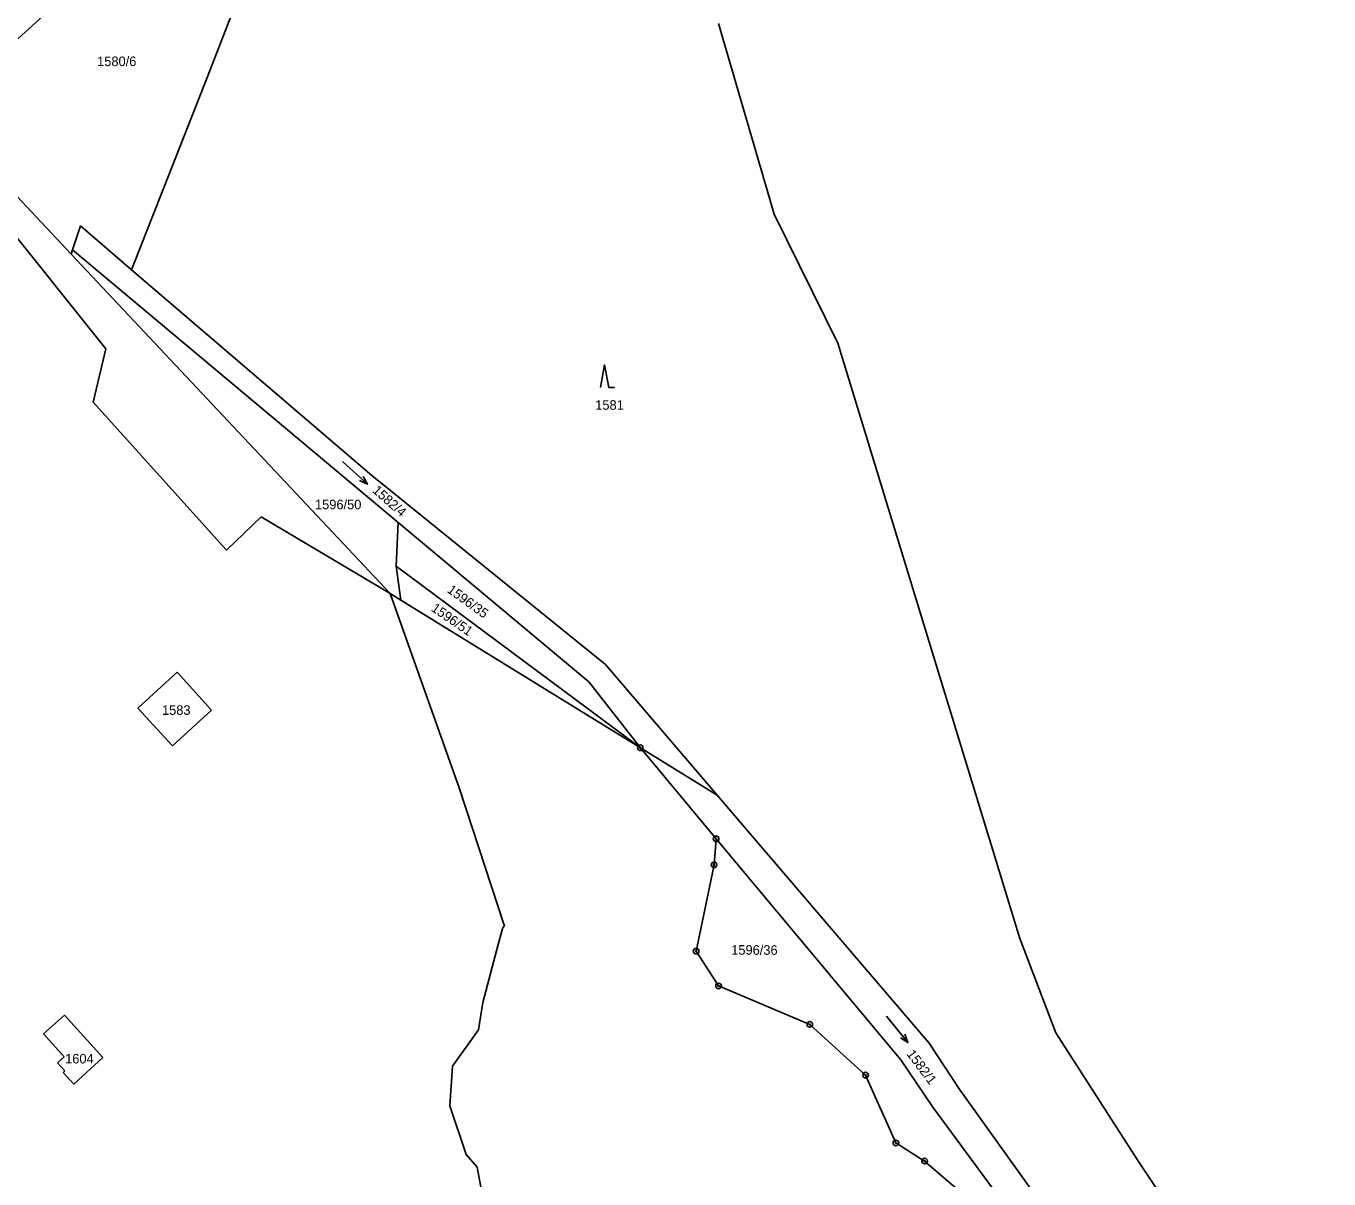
# Model space of a CAD drawing. Extents: x -763296 to -761805, y -1153670 to -1152034.
# Drawn here: x -762319 to -762088.1, y -1152743.4 to -1152539 of the extents above; entities that cross this region are included whole.
import ezdxf

# ---------------------------------------------------------------- set-up
doc = ezdxf.new("R2010")
doc.units = 0
for name, color, linetype in [('Vrstva 1', 7, 'Continuous'), ('Vrstva 13', 7, 'Continuous'), ('Vrstva 18', 7, 'Continuous'), ('Vrstva 24', 7, 'Continuous'), ('Vrstva 25', 7, 'Continuous'), ('Vrstva 6', 7, 'Continuous')]:
    doc.layers.add(name, color=color, linetype=linetype)

msp = doc.modelspace()

# ---------------------------------------------------------------- linework, layer by layer
at = {"layer": 'Vrstva 1'}
for p, q in [((-762286.79, -1152547.88), (-762265.79, -1152493.82)), ((-762281.64, -1152506.08), (-762334.74, -1152554.22)), ((-762300.3, -1152582.23), (-762286.79, -1152547.88)), ((-762334.74, -1152554.22), (-762311.03, -1152579.45)), ((-762325.29, -1152570.73), (-762304.85, -1152596.27)), ((-762309.34, -1152574.42), (-762310.78, -1152578.71)), ((-762300.3, -1152582.23), (-762309.34, -1152574.42)), ((-762310.78, -1152578.71), (-762311.03, -1152579.45)), ((-762311.03, -1152579.45), (-762254.48, -1152639.62)), ((-762310.78, -1152578.71), (-762253.04, -1152627.01)), ((-762257.74, -1152618.69), (-762300.3, -1152582.23)), ((-762304.85, -1152596.27), (-762307.08, -1152605.73)), ((-762307.08, -1152605.73), (-762283.49, -1152631.91)), ((-762252.83, -1152622.66), (-762257.74, -1152618.69)), ((-762216.32, -1152652.19), (-762252.83, -1152622.66)), ((-762283.49, -1152631.91), (-762277.31, -1152626)), ((-762277.31, -1152626), (-762254.48, -1152639.62)), ((-762253.04, -1152627.01), (-762219.26, -1152655.26)), ((-762254.48, -1152639.62), (-762242.21, -1152674.08)), ((-762254.48, -1152639.62), (-762252.59, -1152640.78)), ((-762252.59, -1152640.78), (-762210.12, -1152666.97)), ((-762196.53, -1152675.34), (-762216.32, -1152652.19)), ((-762299.19, -1152659.96), (-762292.2, -1152653.59)), ((-762292.2, -1152653.59), (-762286.15, -1152660.28)), ((-762219.26, -1152655.26), (-762210.12, -1152666.97)), ((-762293.04, -1152666.63), (-762299.19, -1152659.96)), ((-762286.15, -1152660.28), (-762293.04, -1152666.63)), ((-762210.12, -1152666.97), (-762196.69, -1152683.11)), ((-762242.21, -1152674.08), (-762234.19, -1152698.59)), ((-762158.95, -1152719.31), (-762196.53, -1152675.34)), ((-762196.69, -1152683.11), (-762197.06, -1152687.71)), ((-762196.69, -1152683.11), (-762163.94, -1152722.26)), ((-762197.06, -1152687.71), (-762200.24, -1152703.02)), ((-762234.51, -1152698.81), (-762235.3, -1152701.85)), ((-762234.19, -1152698.59), (-762234.51, -1152698.81)), ((-762235.3, -1152701.85), (-762238.05, -1152712.09)), ((-762200.24, -1152703.02), (-762196.26, -1152709.19)), ((-762196.26, -1152709.19), (-762180.08, -1152716)), ((-762238.05, -1152712.09), (-762238.79, -1152716.94)), ((-762315.89, -1152717.69), (-762312.16, -1152714.39)), ((-762312.16, -1152714.39), (-762305.42, -1152721.86)), ((-762312.25, -1152721.77), (-762315.89, -1152717.69)), ((-762238.79, -1152716.94), (-762243.43, -1152723.42)), ((-762180.08, -1152716), (-762170.19, -1152724.99)), ((-762153.61, -1152727.41), (-762158.95, -1152719.31)), ((-762313.42, -1152722.8), (-762312.25, -1152721.77)), ((-762305.42, -1152721.86), (-762310.55, -1152726.6)), ((-762163.94, -1152722.26), (-762158.28, -1152730.66)), ((-762312.1, -1152724.25), (-762313.42, -1152722.8)), ((-762312.43, -1152724.55), (-762312.1, -1152724.25)), ((-762310.55, -1152726.6), (-762312.43, -1152724.55)), ((-762243.43, -1152723.42), (-762243.86, -1152730.44)), ((-762170.19, -1152724.99), (-762164.82, -1152737.02)), ((-762153.61, -1152727.41), (-762102.96, -1152798.06)), ((-762243.86, -1152730.44), (-762241.02, -1152739.07)), ((-762158.28, -1152730.66), (-762135.37, -1152761.7)), ((-762164.82, -1152737.02), (-762159.73, -1152740.22)), ((-762241.02, -1152739.07), (-762239.03, -1152741.3)), ((-762159.73, -1152740.22), (-762143.61, -1152754.05)), ((-762239.03, -1152741.3), (-762236.07, -1152757.56))]:
    msp.add_line(p, q, dxfattribs=at)
at = {"layer": 'Vrstva 13'}
for p, q in [((-762186.41, -1152572.39), (-762196.29, -1152538.57)), ((-762175.1, -1152595.25), (-762186.41, -1152572.39)), ((-762175.1, -1152595.25), (-762142.88, -1152700.8)), ((-762142.88, -1152700.8), (-762136.49, -1152717.47)), ((-762121.93, -1152740.13), (-762136.49, -1152717.47)), ((-762121.93, -1152740.13), (-762088.07, -1152790.67))]:
    msp.add_line(p, q, dxfattribs=at)
at = {"layer": 'Vrstva 24'}
for centre, radius in [((-762210.12, -1152666.97), 0.5), ((-762210.12, -1152666.97), 0.1), ((-762196.69, -1152683.11), 0.5), ((-762196.69, -1152683.11), 0.1), ((-762197.06, -1152687.71), 0.5), ((-762197.06, -1152687.71), 0.1), ((-762200.24, -1152703.02), 0.5), ((-762200.24, -1152703.02), 0.1), ((-762196.26, -1152709.19), 0.5), ((-762196.26, -1152709.19), 0.1), ((-762180.08, -1152716), 0.5), ((-762180.08, -1152716), 0.1), ((-762170.19, -1152724.99), 0.5), ((-762170.19, -1152724.99), 0.1), ((-762164.82, -1152737.02), 0.5), ((-762164.82, -1152737.02), 0.1), ((-762159.73, -1152740.22), 0.5), ((-762159.73, -1152740.22), 0.1)]:
    msp.add_circle(centre, radius, dxfattribs=at)
at = {"layer": 'Vrstva 25'}
for points in [[(-762217.18, -1152603.11), (-762216.48, -1152599.11), (-762215.68, -1152603.11), (-762214.68, -1152603.11)], [(-762262.903, -1152616.206), (-762258.457, -1152620.234), (-762259.233, -1152618.857)], [(-762258.457, -1152620.234), (-762259.904, -1152619.598)], [(-762166.468, -1152714.548), (-762162.692, -1152719.212), (-762163.248, -1152717.731)], [(-762162.692, -1152719.212), (-762164.025, -1152718.36)]]:
    msp.add_lwpolyline(points, dxfattribs=at)
at = {"layer": 'Vrstva 6'}
for p, q in [((-762253.04, -1152627.01), (-762253.41, -1152634.77)), ((-762253.41, -1152634.77), (-762210.12, -1152666.97)), ((-762253.41, -1152634.77), (-762252.59, -1152640.78)), ((-762210.12, -1152666.97), (-762196.53, -1152675.34))]:
    msp.add_line(p, q, dxfattribs=at)

# ---------------------------------------------------------------- texts
at = {"layer": 'Vrstva 18'}
for s, p in [('1580/6', (-762306.405, -1152546.13)), ('1581', (-762218.111, -1152607.05)), ('1596/50', (-762267.784, -1152624.69)), ('1583', (-762294.906, -1152661.13)), ('1604', (-762312.072, -1152722.93))]:
    msp.add_text(s, height=1.7, dxfattribs=at).set_placement(p)
for s, rotation, p in [('1582/4', 318.56453, (-762257.74, -1152621.545)), ('1596/35', 324.12223, (-762244.503, -1152639.288)), ('1596/51', 325.38273, (-762247.334, -1152642.579)), ('1596/36', 359.81749, (-762194.008, -1152703.645)), ('1582/1', 306.99079, (-762163.02, -1152721.266))]:
    msp.add_text(s, height=1.7, rotation=rotation, dxfattribs=at).set_placement(p)

doc.saveas('drawing.dxf')
